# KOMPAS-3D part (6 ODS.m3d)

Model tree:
1. Плоскость XY
2. Плоскость ZX
3. Плоскость ZY
4. Ось X
5. Ось Y
6. Ось Z
7. Начало координат
8. Эскиз:1
9. Операция вращения:1
     Угол 1 = 360; Угол 2 = 360
10. Эскиз:2
11. Операция выдавливания:1
     Расстояние 1 = 28; Расстояние 2 = 10
12. Эскиз:3
13. Операция выдавливания:2
     Расстояние 1 = 28; Расстояние 2 = 20.5
14. Эскиз:4
15. Операция выдавливания:3
     Расстояние 1 = 20; Расстояние 2 = 30
16. Скругление:1
     Радиус = 1
17. Скругление:2
     Радиус = 0.5
18. Фаска:1
     Угол = 45; Длина 1 = 0.5; Длина 2 = 0.5
19. Эскиз:5
20. Операция вращения:2
     Угол 1 = 360; Угол 2 = 360
21. Эскиз:6
22. Вырезать элемент выдавливания:1
     Расстояние 2 = 10; Расстояние 1 = 1
23. Эскиз:7
24. Операция вращения:3
     Угол 1 = 360; Угол 2 = 360
25. Эскиз:8
26. Вырезать элемент выдавливания:2
     Расстояние 2 = 20; Расстояние 1 = 1
27. Эскиз:9
28. Операция вращения:4
     Угол 1 = 360; Угол 2 = 360

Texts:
  Линия-выноска #1
  Линия-выноска #2
  Линия-выноска #3
  Отклонения формы и база
  Марка координационной оси
  Марка/позиционное обозначение с линией-выноской
  Марка/позиционное обозначение на линии
  Марка/позиционное обозначение без линии-выноски
  Текст на чертеже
